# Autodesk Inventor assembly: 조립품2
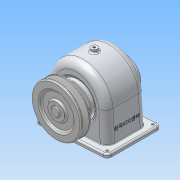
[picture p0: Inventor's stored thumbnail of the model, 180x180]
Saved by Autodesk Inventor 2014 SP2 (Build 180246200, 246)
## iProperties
Created: 2016-01
Part Number: 조립품2
Document SubType Name: Assembly
Designer: User
Author: User
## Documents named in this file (16)
- C:\Documents and Settings\User\My Documents\Inventor\460106V1017\조립품2.iam
- C:\Documents and Settings\User\My Documents\Inventor\460106V1017\본체.ipt
- C:\Documents and Settings\User\My Documents\Inventor\460106V1017\축.ipt
- C:\Documents and Settings\User\My Documents\Inventor\460106V1017\뒤커버.ipt
- C:\Documents and Settings\User\My Documents\Inventor\460106V1017\베어링 6203.ipt
- C:\Documents and Settings\User\My Documents\Inventor\460106V1017\오일씰 28 40 8.ipt
- C:\Documents and Settings\User\My Documents\Inventor\460106V1017\부시1.ipt
- C:\Documents and Settings\User\My Documents\Inventor\460106V1017\부시2.ipt
- C:\Documents and Settings\User\My Documents\Inventor\460106V1017\스퍼기어.ipt
- C:\Documents and Settings\User\My Documents\Inventor\460106V1017\키 - 6 x 6 x 22.ipt
- C:\Documents and Settings\User\My Documents\Inventor\460106V1017\키 - 5 x 5 x 18.ipt
- C:\Documents and Settings\User\My Documents\Inventor\460106V1017\앞커버.ipt
- C:\Documents and Settings\User\My Documents\Inventor\460106V1017\V-벨트풀리.ipt
- C:\Documents and Settings\User\My Documents\Inventor\460106V1017\멈춤나사 - M4x10.ipt
- C:\Documents and Settings\User\My Documents\Inventor\460106V1017\볼트 M3 x 10.ipt
- C:\Documents and Settings\User\My Documents\Inventor\460106V1017\볼트 M3 x 8.ipt
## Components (9 placed, 3 different names)
1. V-벨트풀리:1
2. ISO 4762 M3 x 8:1
3. ISO 4762 M3 x 10:1
4. ISO 4762 M3 x 8:2
5. ISO 4762 M3 x 10:2
6. ISO 4762 M3 x 8:3
7. ISO 4762 M3 x 10:3
8. ISO 4762 M3 x 8:4
9. ISO 4762 M3 x 10:4
